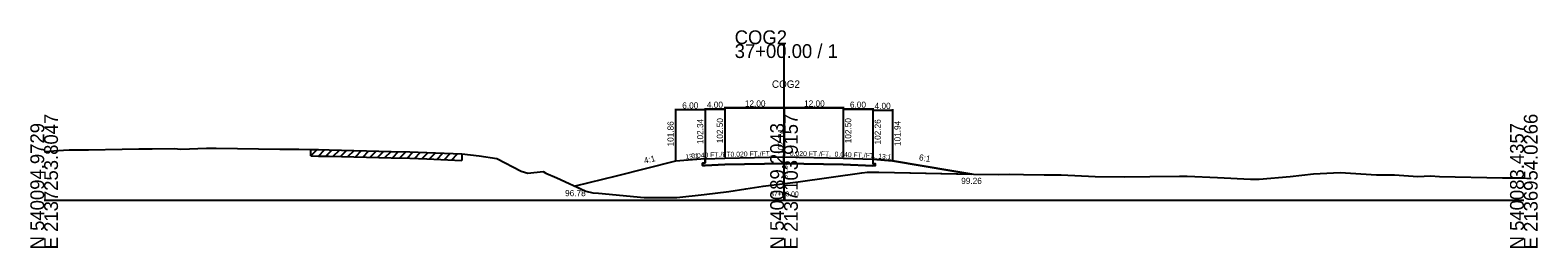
# Model space of a CAD drawing. Extents: x -13397 to 2303, y -10 to 39059.
# Drawn here: x 997.2 to 1302.8, y 13990.3 to 14034.4 of the extents above; entities that cross this region are included whole.
import ezdxf

# ---------------------------------------------------------------- set-up
doc = ezdxf.new("R2010")
doc.units = 0
for name, color, linetype in [('Level 5', 7, 'Continuous'), ('Level 53', 7, 'Continuous'), ('Level 54', 7, 'Continuous'), ('Level 55', 7, 'Continuous'), ('Level 7', 7, 'Continuous'), ('RD_GPK_XS_Cell', 7, 'Continuous'), ('RD_XS_EwShp', 7, 'Continuous'), ('RD_XS_ExGround', 7, 'Continuous'), ('RD_XS_ExPaveRet', 7, 'Continuous'), ('RD_XS_Pave', 7, 'Continuous'), ('RD_XS_TX_Baseline', 7, 'Continuous'), ('RD_XS_TX_Elev_EX', 7, 'Continuous'), ('RD_XS_TX_Elev_PR', 7, 'Continuous'), ('RD_XS_TX_Station', 7, 'Continuous')]:
    doc.layers.add(name, color=color, linetype=linetype)

msp = doc.modelspace()

# ---------------------------------------------------------------- linework, layer by layer
at = {"layer": 'Level 5'}
for p, q in [((1134, 14007.51), (1133.5, 14007.49)), ((1133.5, 14007.49), (1133.5, 14006.99)), ((1133.5, 14006.99), (1134, 14007.01)), ((1134, 14008.34), (1134, 14007.51)), ((1138, 14007.17), (1134, 14007.01)), ((1138, 14007.17), (1134, 14007.01)), ((1138, 14007.17), (1134, 14007.01)), ((1134, 14007.01), (1138, 14007.17)), ((1150, 14007.41), (1138, 14007.17)), ((1150, 14007.41), (1138, 14007.17)), ((1150, 14007.41), (1138, 14007.17)), ((1138, 14007.17), (1150, 14007.41)), ((1138, 14007.17), (1150, 14007.41)), ((1162, 14007.17), (1150, 14007.41)), ((1162, 14007.17), (1150, 14007.41)), ((1150, 14007.41), (1162, 14007.17)), ((1150, 14007.41), (1162, 14007.17)), ((1150, 14007.41), (1162, 14007.17)), ((1168, 14006.93), (1162, 14007.17)), ((1162, 14007.17), (1168, 14006.93)), ((1162, 14007.17), (1168, 14006.93)), ((1162, 14007.17), (1168, 14006.93)), ((1168, 14008.26), (1168, 14007.43)), ((1168, 14007.43), (1168.5, 14007.41)), ((1168.5, 14006.91), (1168, 14006.93)), ((1168.5, 14007.41), (1168.5, 14006.91))]:
    msp.add_line(p, q, dxfattribs=at)
at = {"layer": 'Level 54'}
for p, q in [((1134, 14018.65), (1134, 14008.54)), ((1134, 14018.65), (1134, 14008.54)), ((1134, 14018.65), (1134, 14008.54)), ((1134, 14018.65), (1134, 14008.54)), ((1138, 14018.89), (1138, 14008.7)), ((1138, 14018.89), (1138, 14008.7)), ((1138, 14018.89), (1138, 14008.7)), ((1138, 14018.89), (1138, 14008.7)), ((1138, 14018.89), (1138, 14008.7)), ((1138, 14018.69), (1150, 14018.69)), ((1138, 14018.69), (1150, 14018.69)), ((1138, 14018.69), (1150, 14018.69)), ((1150, 14018.69), (1138, 14018.69)), ((1150, 14018.69), (1138, 14018.69)), ((1138, 14018.65), (1138, 14008.7)), ((1138, 14018.65), (1138, 14008.7)), ((1138, 14018.65), (1138, 14008.7)), ((1138, 14018.65), (1138, 14008.7)), ((1150, 14018.89), (1150, 14008.94)), ((1150, 14018.89), (1150, 14008.94)), ((1150, 14018.89), (1150, 14008.94)), ((1150, 14018.89), (1150, 14008.94)), ((1150, 14018.89), (1150, 14008.94)), ((1150, 14018.89), (1150, 14008.94)), ((1150, 14018.89), (1150, 14008.94)), ((1150, 14018.89), (1150, 14008.94)), ((1150, 14018.89), (1150, 14008.94)), ((1150, 14018.89), (1150, 14008.94)), ((1150, 14018.69), (1162, 14018.69)), ((1150, 14018.69), (1162, 14018.69)), ((1162, 14018.69), (1150, 14018.69)), ((1162, 14018.69), (1150, 14018.69)), ((1162, 14018.69), (1150, 14018.69)), ((1162, 14018.89), (1162, 14008.7)), ((1162, 14018.89), (1162, 14008.7)), ((1162, 14018.89), (1162, 14008.7)), ((1162, 14018.89), (1162, 14008.7)), ((1162, 14018.89), (1162, 14008.7)), ((1162, 14018.65), (1162, 14008.7)), ((1162, 14018.65), (1162, 14008.7)), ((1162, 14018.65), (1162, 14008.7)), ((1162, 14018.65), (1162, 14008.7)), ((1168, 14018.65), (1168, 14008.46)), ((1168, 14018.65), (1168, 14008.46)), ((1168, 14018.65), (1168, 14008.46)), ((1168, 14018.65), (1168, 14008.46)), ((1128, 14018.49), (1128, 14008.06)), ((1134, 14018.29), (1128, 14018.29)), ((1134, 14018.49), (1134, 14008.54)), ((1134, 14018.45), (1138, 14018.45)), ((1134, 14018.45), (1138, 14018.45)), ((1134, 14018.45), (1138, 14018.45)), ((1138, 14018.45), (1134, 14018.45)), ((1162, 14018.45), (1168, 14018.45)), ((1168, 14018.45), (1162, 14018.45)), ((1168, 14018.45), (1162, 14018.45)), ((1168, 14018.45), (1162, 14018.45)), ((1168, 14018.41), (1168, 14008.46)), ((1168, 14018.21), (1172, 14018.21)), ((1172, 14018.41), (1172, 14008.14))]:
    msp.add_line(p, q, dxfattribs=at)
at = {"layer": 'Level 7'}
for p, q in [((1128, 14007.86), (1116, 14004.86)), ((1134, 14008.34), (1128, 14007.86)), ((1168, 14008.26), (1172, 14007.94)), ((1172, 14007.94), (1184, 14005.94)), ((1116, 14004.86), (1107.69, 14002.78)), ((1184, 14005.94), (1188.08, 14005.26))]:
    msp.add_line(p, q, dxfattribs=at)
at = {"layer": 'RD_GPK_XS_Cell'}
for p, q in [((1150, 14000), (1150, 14031.59)), ((1000, 14000), (1150, 14000)), ((1150, 14000), (1300, 14000))]:
    msp.add_line(p, q, dxfattribs=at)
at = {"layer": 'RD_XS_EwShp'}
msp.add_lwpolyline([(1168, 14006.93), (1162, 14007.17), (1150, 14007.41), (1138, 14007.17), (1134, 14007.01), (1133.5, 14006.99), (1133.5, 14007.49), (1134, 14007.51), (1134, 14008.34), (1128, 14007.86), (1116, 14004.86), (1107.69, 14002.78), (1109.79, 14001.81), (1111.25, 14001.47), (1112.41, 14001.38), (1121.68, 14000.53), (1128.27, 14000.52), (1133.82, 14001.15), (1138.79, 14001.73), (1142.29, 14002.29), (1145.78, 14002.83), (1150.17, 14003.35), (1152.88, 14003.69), (1165.77, 14005.5), (1166.95, 14005.66), (1167.85, 14005.67), (1169.21, 14005.63), (1188.08, 14005.26), (1184, 14005.94), (1172, 14007.94), (1168, 14008.26), (1168, 14007.43), (1168.5, 14007.41), (1168.5, 14006.91)], close=True, dxfattribs=at)
at = {"layer": 'RD_XS_ExGround'}
for p, q in [((1000, 14009.86), (1003.91, 14010.09)), ((1003.91, 14010.09), (1005.1, 14010.16)), ((1005.1, 14010.16), (1008.96, 14010.18)), ((1008.96, 14010.18), (1015.8, 14010.28)), ((1015.8, 14010.28), (1019.19, 14010.36)), ((1019.19, 14010.36), (1021.9, 14010.39)), ((1021.9, 14010.39), (1026.35, 14010.45)), ((1026.35, 14010.45), (1027.68, 14010.29)), ((1027.68, 14010.29), (1032.88, 14010.48)), ((1032.88, 14010.48), (1034.84, 14010.53)), ((1034.84, 14010.53), (1047.75, 14010.32)), ((1047.75, 14010.32), (1051.64, 14010.3)), ((1051.64, 14010.3), (1054.09, 14010.25)), ((1054.09, 14010.25), (1055.61, 14010.22)), ((1055.61, 14010.22), (1057.77, 14010.19)), ((1057.77, 14010.19), (1070.35, 14009.86)), ((1070.35, 14009.86), (1074.16, 14009.77)), ((1074.16, 14009.77), (1077.6, 14009.62)), ((1077.6, 14009.62), (1084.71, 14009.33)), ((1084.71, 14009.33), (1088.18, 14008.95)), ((1088.18, 14008.95), (1091.78, 14008.42)), ((1091.78, 14008.42), (1096.72, 14005.87)), ((1096.72, 14005.87), (1098.03, 14005.44)), ((1098.03, 14005.44), (1101.18, 14005.76)), ((1101.18, 14005.76), (1101.69, 14005.45)), ((1101.69, 14005.45), (1103.92, 14004.53)), ((1103.92, 14004.53), (1109.79, 14001.81)), ((1145.78, 14002.83), (1150.17, 14003.35)), ((1150.17, 14003.35), (1152.88, 14003.69)), ((1152.88, 14003.69), (1165.77, 14005.5)), ((1165.77, 14005.5), (1166.95, 14005.66)), ((1166.95, 14005.66), (1167.85, 14005.67)), ((1167.85, 14005.67), (1169.21, 14005.63)), ((1169.21, 14005.63), (1188.39, 14005.25)), ((1188.39, 14005.25), (1193.42, 14005.17)), ((1193.42, 14005.17), (1195.78, 14005.23)), ((1195.78, 14005.23), (1198.58, 14005.18)), ((1198.58, 14005.18), (1202.72, 14005.13)), ((1202.72, 14005.13), (1206.2, 14005.09)), ((1206.2, 14005.09), (1213.11, 14004.75)), ((1213.11, 14004.75), (1218.99, 14004.71)), ((1218.99, 14004.71), (1224.16, 14004.76)), ((1224.16, 14004.76), (1230.21, 14004.82)), ((1230.21, 14004.82), (1231.77, 14004.81)), ((1231.77, 14004.81), (1237.86, 14004.54)), ((1237.86, 14004.54), (1244.55, 14004.25)), ((1244.55, 14004.25), (1245.35, 14004.22)), ((1245.35, 14004.22), (1246.37, 14004.21)), ((1246.37, 14004.21), (1252.6, 14004.78)), ((1252.6, 14004.78), (1257.34, 14005.3)), ((1257.34, 14005.3), (1262.73, 14005.61)), ((1262.73, 14005.61), (1270.12, 14005.13)), ((1270.12, 14005.13), (1273.76, 14005.1)), ((1273.76, 14005.1), (1278.52, 14004.76)), ((1278.52, 14004.76), (1281.05, 14004.89)), ((1281.05, 14004.89), (1282.9, 14004.75)), ((1282.9, 14004.75), (1295.67, 14004.53)), ((1295.67, 14004.53), (1300, 14004.48)), ((1109.79, 14001.81), (1111.25, 14001.47)), ((1111.25, 14001.47), (1112.41, 14001.38)), ((1112.41, 14001.38), (1121.68, 14000.53)), ((1121.68, 14000.53), (1128.27, 14000.52)), ((1128.27, 14000.52), (1133.82, 14001.15)), ((1133.82, 14001.15), (1138.79, 14001.73)), ((1138.79, 14001.73), (1142.29, 14002.29)), ((1142.29, 14002.29), (1145.78, 14002.83))]:
    msp.add_line(p, q, dxfattribs=at)
at = {"layer": 'RD_XS_ExPaveRet'}
for p, q in [((1054.09, 14008.95), (1054.09, 14010.25)), ((1054.09, 14008.95), (1055.36, 14010.23)), ((1055.59, 14008.92), (1056.87, 14010.2)), ((1057.09, 14008.9), (1058.36, 14010.17)), ((1058.59, 14008.87), (1059.85, 14010.13)), ((1060.09, 14008.83), (1061.35, 14010.09)), ((1061.59, 14008.79), (1062.85, 14010.05)), ((1063.09, 14008.75), (1064.35, 14010.01)), ((1064.59, 14008.71), (1065.85, 14009.98)), ((1066.09, 14008.67), (1067.35, 14009.94)), ((1067.59, 14008.63), (1068.85, 14009.9)), ((1069.09, 14008.59), (1070.35, 14009.86)), ((1070.59, 14008.55), (1071.86, 14009.82)), ((1072.09, 14008.52), (1073.36, 14009.79)), ((1073.59, 14008.48), (1074.84, 14009.74)), ((1075.09, 14008.43), (1076.33, 14009.67)), ((1076.59, 14008.36), (1077.83, 14009.61)), ((1078.09, 14008.3), (1079.33, 14009.55)), ((1079.59, 14008.24), (1080.83, 14009.49)), ((1081.09, 14008.18), (1082.33, 14009.42)), ((1054.09, 14008.95), (1055.61, 14008.92)), ((1055.61, 14008.92), (1057.77, 14008.89)), ((1057.77, 14008.89), (1070.35, 14008.56)), ((1070.35, 14008.56), (1074.16, 14008.47)), ((1074.16, 14008.47), (1077.6, 14008.32)), ((1077.6, 14008.32), (1084.71, 14008.03)), ((1082.59, 14008.11), (1083.83, 14009.36)), ((1084.71, 14009.33), (1084.71, 14008.03))]:
    msp.add_line(p, q, dxfattribs=at)
at = {"layer": 'RD_XS_Pave'}
for p, q in [((1134, 14008.34), (1138, 14008.5)), ((1138, 14008.5), (1150, 14008.74)), ((1150, 14008.74), (1162, 14008.5)), ((1162, 14008.5), (1168, 14008.26))]:
    msp.add_line(p, q, dxfattribs=at)

# ---------------------------------------------------------------- texts
at = {"layer": 'Level 53'}
for s, rotation, p in [('101.86', 90, (1127.62, 14010.86)), ('102.34', 90, (1133.62, 14011.34)), ('102.50', 90, (1137.63, 14011.5)), ('102.50', 90, (1137.63, 14011.5)), ('102.50', 90, (1137.63, 14011.5)), ('102.50', 90, (1163.63, 14011.5)), ('102.50', 90, (1163.63, 14011.5)), ('102.50', 90, (1163.63, 14011.5)), ('102.26', 90, (1169.62, 14011.26)), ('101.94', 90, (1173.62, 14010.94)), ('4:1', 14.0362, (1121.76, 14007.33)), ('6:1', 350.5377, (1177.3, 14008.07))]:
    msp.add_text(s, height=1.25, rotation=rotation, dxfattribs=at).set_placement(p)
for s, p in [('99.26', (1185.93, 14003.26)), ('96.78', (1105.61, 14000.78))]:
    msp.add_text(s, height=1.25, dxfattribs=at).set_placement(p)
at = {"layer": 'Level 54'}
for s, p in [('6.00', (1129.37, 14018.54)), ('4.00', (1134.37, 14018.7)), ('4.00', (1134.37, 14018.7)), ('4.00', (1134.37, 14018.7)), ('4.00', (1134.37, 14018.7)), ('12.00', (1142.07, 14018.94)), ('12.00', (1142.07, 14018.94)), ('12.00', (1142.07, 14018.94)), ('12.00', (1142.07, 14018.94)), ('12.00', (1142.07, 14018.94)), ('12.00', (1154.07, 14018.94)), ('12.00', (1154.07, 14018.94)), ('12.00', (1154.07, 14018.94)), ('12.00', (1154.07, 14018.94)), ('12.00', (1154.07, 14018.94)), ('6.00', (1163.37, 14018.7)), ('6.00', (1163.37, 14018.7)), ('6.00', (1163.37, 14018.7)), ('6.00', (1163.37, 14018.7)), ('4.00', (1168.37, 14018.46))]:
    msp.add_text(s, height=1.25, dxfattribs=at).set_placement(p)
at = {"layer": 'Level 55'}
for s, rotation, p in [('13:1', 4.5739, (1130.03, 14008.27)), ('0.040 FT./FT.', 2.2906, (1131.22, 14008.48)), ('0.040 FT./FT.', 2.2906, (1131.22, 14008.48)), ('0.040 FT./FT.', 2.2906, (1131.22, 14008.48)), ('0.040 FT./FT.', 2.2906, (1131.22, 14008.48)), ('0.020 FT./FT.', 1.1458, (1139.17, 14008.77)), ('0.020 FT./FT.', 1.1458, (1139.17, 14008.77)), ('0.020 FT./FT.', 1.1458, (1139.17, 14008.77)), ('0.020 FT./FT.', 1.1458, (1139.17, 14008.77)), ('0.020 FT./FT.', 1.1458, (1139.17, 14008.77)), ('0.020 FT./FT.', 358.8542, (1151.18, 14008.97)), ('0.020 FT./FT.', 358.8542, (1151.18, 14008.97)), ('0.020 FT./FT.', 358.8542, (1151.18, 14008.97)), ('0.020 FT./FT.', 358.8542, (1151.18, 14008.97)), ('0.020 FT./FT.', 358.8542, (1151.18, 14008.97)), ('0.040 FT./FT.', 357.7094, (1160.24, 14008.82)), ('0.040 FT./FT.', 357.7094, (1160.24, 14008.82)), ('0.040 FT./FT.', 357.7094, (1160.24, 14008.82)), ('0.040 FT./FT.', 357.7094, (1160.24, 14008.82)), ('13:1', 355.4261, (1169.07, 14008.43))]:
    msp.add_text(s, height=1, rotation=rotation, dxfattribs=at).set_placement(p)
at = {"layer": 'RD_GPK_XS_Cell'}
for s, p in [('COG2', (1140, 14031.59)), ('37+00.00 / 1', (1140, 14028.79))]:
    msp.add_text(s, height=2.8, dxfattribs=at).set_placement(p)
for s, p in [('E 2137253.8047', (1002.8, 13990)), ('E 2137103.9157', (1152.8, 13990)), ('E 2136954.0266', (1302.8, 13990)), ('N 540094.9729', (1000, 13990)), ('N 540089.2043', (1150, 13990)), ('N 540083.4357', (1300, 13990))]:
    msp.add_text(s, height=2.8, rotation=90, dxfattribs=at).set_placement(p)
at = {"layer": 'RD_XS_TX_Baseline'}
msp.add_text('COG2', height=1.5, dxfattribs=at).set_placement((1147.55, 14022.74))
at = {"layer": 'RD_XS_TX_Elev_EX'}
msp.add_text('97.33', height=1, rotation=90, dxfattribs=at).set_placement((1150.75, 14004.33))
at = {"layer": 'RD_XS_TX_Elev_PR'}
msp.add_text(' 102.74', height=1.25, rotation=90, dxfattribs=at).set_placement((1150, 14008.74))
at = {"layer": 'RD_XS_TX_Station'}
msp.add_text('37+00.00', height=1, dxfattribs=at).set_placement((1147.19, 14000.74))

doc.saveas('drawing.dxf')
